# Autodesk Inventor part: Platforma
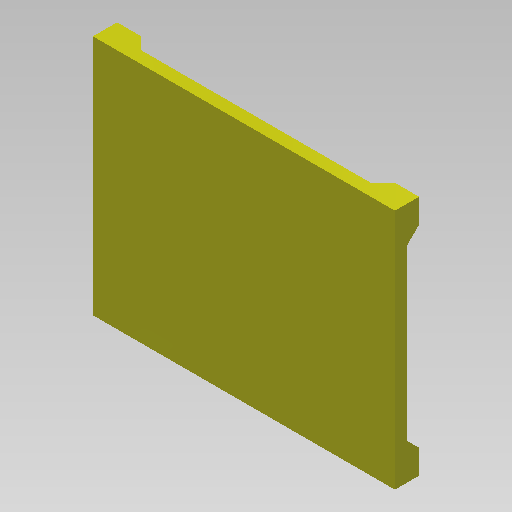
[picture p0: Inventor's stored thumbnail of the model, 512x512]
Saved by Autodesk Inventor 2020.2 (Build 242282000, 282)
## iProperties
Created: 2014-06
Part Number: Platforma
Material: Ogólny
Document SubType Name: Modeling
Designer: F.Stasiak
Density: 1 g/cm^3
Appearance: Gładkie - żółte
Catalog Web Link: www.expertbooks.pl
Manager: www.cadconsulting.pl
Company: Fabian Stasiak CAD Consulting
Author: F.Stasiak
Subject: Zbiór ćwiczeń. Autodesk Inventor 2020. Kurs Professional
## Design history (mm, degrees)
sketch "Szkic1"
  geometry: L1 (-1250, 1000)-(1250, 1000); L2 (1250, 1000)-(1250, -1000); L3 (1250, -1000)-(-1250, -1000); L4 (-1250, -1000)-(-1250, 1000); L5 (-1250, 1000)-(1250, -1000); L6 (1250, 1000)-(-1250, -1000); 1 further point
  constraints: 12 end point, 2 midpoint, 2 parallel, 1 horizontal, 1 perpendicular
  dimensions: "d0" = 2500 distance of L2.end L3.end; "d1" = 2000 distance of L1.end L2.end
extrude "Wyciągnięcie proste1" new body sketch "Szkic1" distance "d2" = 200; taper "d3" = 0 deg
feature "Skorupa1" dims "d4" = 10
sketch "Szkic2"
  geometry: L1 (0, 2000)-(0, 0) reference; L2 (200, 2000)-(200, 0) reference; L3 (0, 2000)-(200, 2000) reference; L4 (200, 200)-(100, 300); L5 (100, 300)-(100, 1700); L6 (100, 1700)-(200, 1800); 3 further points
  constraints: 6 end point, 2 midpoint, 2 perpendicular, 2 point on line, 1 horizontal alignment
  dimensions: "d5" = 100 distance between parallel lines of L1 L5; "d6" = 135 deg angle of L5 L4; "d7" = 200 distance of L2.end L4.start
extrude "Wyciągnięcie proste2" cut sketch "Szkic2" extent not by distance; stored distance "d8" = 200; taper "d9" = 0 deg
sketch "Szkic3"
  geometry: L1 (0, 2300)-(0, -200); L2 (200, 2300)-(200, -200); L3 (0, 2300)-(200, 2300); L4 (200, 0)-(100, 100); L5 (100, 100)-(100, 2000); L6 (100, 2000)-(200, 2100); L7 (0, 2300)-(0, -200) reference; L8 (0, -200)-(200, -200) reference; L9 (200, 2300)-(200, -200) reference; L10 (0, 2300)-(200, 2300) reference; L11 (200, -200)-(0, -200); 4 further points
  constraints: 14 end point, 4 midpoint, 3 collinear, 2 perpendicular, 2 point on line, 1 horizontal alignment, 1 parallel
  dimensions: "d11" = 100 distance between parallel lines of L1 L5; "d10" = 135 deg angle of L5 L4; "d12" = 200 distance of L2.end L4.start
extrude "Wyciągnięcie proste3" cut sketch "Szkic3" extent not by distance; taper "d14" = 0 deg; stored distance "d15" = 200
node "Bryła1"
